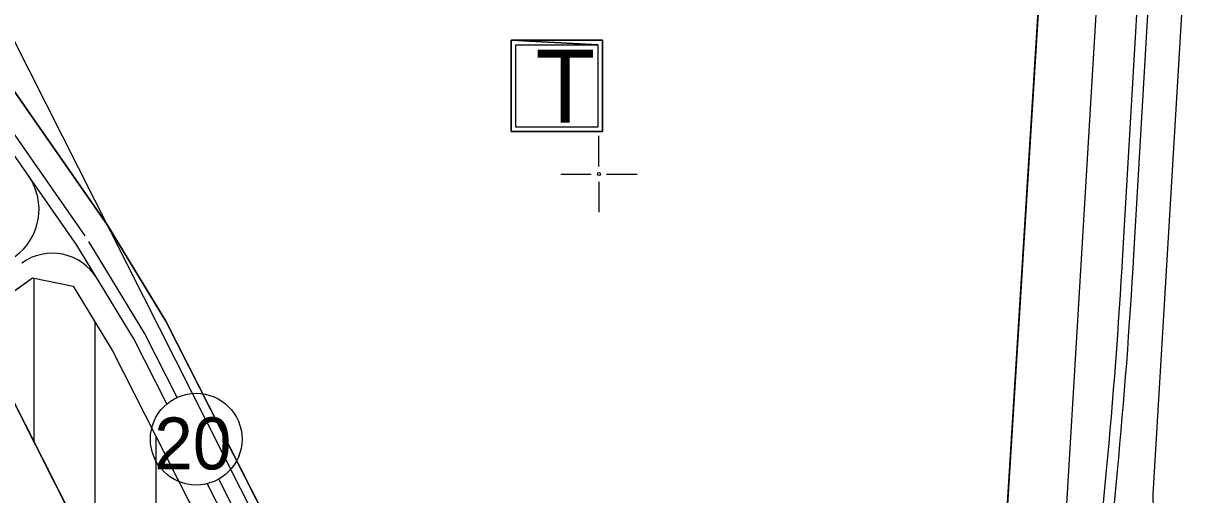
# Model space of a CAD drawing. Extents: x 419109 to 421295, y 4452223 to 4457798.
# Drawn here: x 419811.7 to 420199.2, y 4454395.3 to 4454549.2 of the extents above; entities that cross this region are included whole.
import ezdxf

# ---------------------------------------------------------------- set-up
doc = ezdxf.new("R2010")
doc.units = 0
for name, color, linetype in [('ADA', 7, 'Continuous'), ('ADAKENARI', 7, 'Continuous'), ('Default', 7, 'Continuous'), ('KALDIRIM', 7, 'Continuous'), ('KD_DAIRE', 7, 'Continuous'), ('KD_YGEN', 7, 'Continuous'), ('PAFTALAMA', 7, 'Continuous'), ('PL_KON_MEV_200', 7, 'Continuous'), ('PL_SAY_MES_TEKNIK', 7, 'Continuous'), ('PL_TICARET', 7, 'Continuous'), ('RAYLI_TOPLU_TAŞIMA_HATTI', 7, 'Continuous'), ('SEMBOL', 7, 'Continuous'), ('SN_KENTSEL_DONUSUM', 7, 'Continuous'), ('TR_AZYOGUNKONUT', 7, 'Continuous'), ('TR_ORTAEGITIM', 7, 'Continuous'), ('TR_TİCARET', 7, 'Continuous')]:
    doc.layers.add(name, color=color, linetype=linetype)

# ---------------------------------------------------------------- blocks, each defined once
blk = doc.blocks.new('POINT_DISPLAY')
at = {"layer": 'Default'}
blk.add_line((0, 0), (0, 0), dxfattribs=at)

msp = doc.modelspace()

# ---------------------------------------------------------------- linework, layer by layer
at = {"layer": 'ADA'}
msp.add_line((419834.69, 4454373.46), (419794.95, 4454452.06), dxfattribs=at)
at = {"layer": 'ADAKENARI'}
for p, q in [((420154.76, 4454727.62), (420132.5, 4454371.37)), ((419839.11, 4454483.3), (419792.84, 4454549.61)), ((419858.22, 4454451.9), (419839.11, 4454483.3)), ((419794.95, 4454452.06), (419814.54, 4454466.02)), ((419814.54, 4454466.02), (419827.89, 4454463.28)), ((419827.89, 4454463.28), (419840.74, 4454442.16)), ((419928.05, 4454314.54), (419858.22, 4454451.9)), ((419840.74, 4454442.16), (419908.64, 4454308.59))]:
    msp.add_line(p, q, dxfattribs=at)
at = {"layer": 'KALDIRIM'}
for p, q in [((420170.99, 4454689.69), (420152.75, 4454385.78)), ((420198.17, 4454675.31), (420181.37, 4454395.26)), ((419829.06, 4454476.74), (419770.92, 4454560.06)), ((419831.78, 4454479.83), (419776.14, 4454559.58)), ((419851.23, 4454448.01), (419832.98, 4454477.98)), ((419847.74, 4454446.06), (419829.06, 4454476.74)), ((419861.94, 4454426.94), (419851.23, 4454448.01)), ((419858.54, 4454424.8), (419847.74, 4454446.06)), ((419919.19, 4454314.31), (419875.52, 4454400.22)), ((419915.98, 4454311.8), (419871.79, 4454398.74))]:
    msp.add_line(p, q, dxfattribs=at)
for centre, radius, start, end in [((419797.57, 4454488.46), 19.12, 305.4667, 34.9058), ((419821.02, 4454456.92), 17.17, 31.3287, 125.4668), ((420198.91, 4454394.2), 17.57, 176.5664, 282.4286)]:
    msp.add_arc(centre, radius, start, end, dxfattribs=at)
at = {"layer": 'KD_DAIRE'}
msp.add_circle((419868.16, 4454413.29), 15, dxfattribs=at)
at = {"layer": 'PAFTALAMA'}
for p, q in [((420000, 4454502.5), (420000, 4454512.5)), ((419987.5, 4454500), (419997.5, 4454500)), ((420000, 4454497.5), (420000, 4454487.5)), ((420002.5, 4454500), (420012.5, 4454500))]:
    msp.add_line(p, q, dxfattribs=at)
msp.add_circle((420000, 4454500), 0.5, dxfattribs=at)
at = {"layer": 'PL_KON_MEV_200'}
msp.add_lwpolyline([(419784.23, 4454300.1), (419788.96, 4454351.14), (419834.69, 4454373.46), (419794.95, 4454452.06), (419814.54, 4454466.02), (419827.89, 4454463.28), (419840.74, 4454442.16), (419908.64, 4454308.59), (419903.61, 4454296.74), (419855.94, 4454282.11), (419808.06, 4454263.2), (419775.08, 4454254.34)], close=True, dxfattribs=at)
at = {"layer": 'PL_SAY_MES_TEKNIK'}
msp.add_lwpolyline([(419794.95, 4454452.06), (419834.69, 4454373.46), (419788.96, 4454351.14), (419732.52, 4454323.6), (419711.3, 4454313.25), (419671.81, 4454374.87), (419673.94, 4454375.82), (419676.07, 4454376.79), (419678.17, 4454377.79), (419680.27, 4454378.81), (419682.35, 4454379.86), (419684.42, 4454380.94), (419686.47, 4454382.05), (419688.51, 4454383.18), (419723.16, 4454402.73), (419726.19, 4454404.46), (419729.2, 4454406.24), (419732.18, 4454408.05), (419735.14, 4454409.91), (419738.08, 4454411.8), (419740.99, 4454413.73), (419743.87, 4454415.7), (419746.73, 4454417.71)], close=True, dxfattribs=at)
at = {"layer": 'PL_TICARET'}
msp.add_lwpolyline([(420085.45, 4454703.12), (420039.09, 4454667.79), (420028.1, 4454686.23), (420027.16, 4454685.78), (420013.13, 4454679.08), (419917.2, 4454633.26), (419792.84, 4454549.61), (419839.11, 4454483.3), (419858.22, 4454451.9), (419928.05, 4454314.54), (419940.34, 4454309.33), (420117.41, 4454362.33), (420121.93, 4454364.07), (420126.82, 4454366.86), (420132.5, 4454371.37), (420150.21, 4454654.9), (420133.32, 4454650.02)], dxfattribs=at)
at = {"layer": 'RAYLI_TOPLU_TAŞIMA_HATTI'}
for p, q in [((420171.58, 4454473.78), (420180.42, 4454625.96)), ((420175.18, 4454473.57), (420184.02, 4454625.75)), ((420162.12, 4454359.42), (420166.22, 4454403.1)), ((420167.05, 4454373.45), (420169.8, 4454402.77))]:
    msp.add_line(p, q, dxfattribs=at)
for radius in [1998.2, 2001.8]:
    msp.add_arc((418176.75, 4454589.66), radius, 354.64296, 356.67538, dxfattribs=at)
at = {"layer": 'SEMBOL'}
msp.add_lwpolyline([(419971.29, 4454543.75), (419971.29, 4454513.89), (420001.15, 4454513.89), (420001.15, 4454543.75), (419971.29, 4454543.75), (419999.66, 4454542.25), (419999.66, 4454515.38), (419972.78, 4454515.38), (419972.78, 4454542.25), (419999.66, 4454542.25)], close=True, dxfattribs=at)
at = {"layer": 'SN_KENTSEL_DONUSUM'}
msp.add_line((419931.85, 4454300.11), (419789.03, 4454582.16), dxfattribs=at)
at = {"layer": 'TR_AZYOGUNKONUT'}
for p, q in [((419815.08, 4454412.25), (419815.08, 4454465.91)), ((419835.08, 4454354.15), (419835.08, 4454451.46)), ((419855.08, 4454353.29), (419855.08, 4454413.95))]:
    msp.add_line(p, q, dxfattribs=at)
at = {"layer": 'TR_TİCARET'}
for points in [[(420085.45, 4454703.12), (420039.09, 4454667.79), (420028.1, 4454686.23), (420027.16, 4454685.78), (420013.13, 4454679.08), (419917.2, 4454633.26), (419792.84, 4454549.61), (419839.11, 4454483.3), (419858.22, 4454451.9), (419928.05, 4454314.54), (419940.34, 4454309.33), (420117.41, 4454362.33), (420121.93, 4454364.07), (420126.82, 4454366.86), (420132.5, 4454371.37), (420150.21, 4454654.9)], [(419971.29, 4454543.75), (420001.15, 4454543.75), (420001.15, 4454513.89), (419971.29, 4454513.89), (419971.29, 4454543.75)]]:
    msp.add_lwpolyline(points, dxfattribs=at)

# ---------------------------------------------------------------- block references
at = {"layer": 'TR_ORTAEGITIM', "xscale": 0.1, "yscale": 0.10000000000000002}
msp.add_blockref('POINT_DISPLAY', (419811.81, 4454413.25), dxfattribs=at)

# ---------------------------------------------------------------- texts
at = {"layer": 'KD_YGEN'}
msp.add_text('20', height=17, dxfattribs=at).set_placement((419854.4, 4454403.39))
at = {"layer": 'SEMBOL'}
msp.add_text('T', height=23.89, dxfattribs=at).set_placement((419979.25, 4454516.79))

doc.saveas('drawing.dxf')
